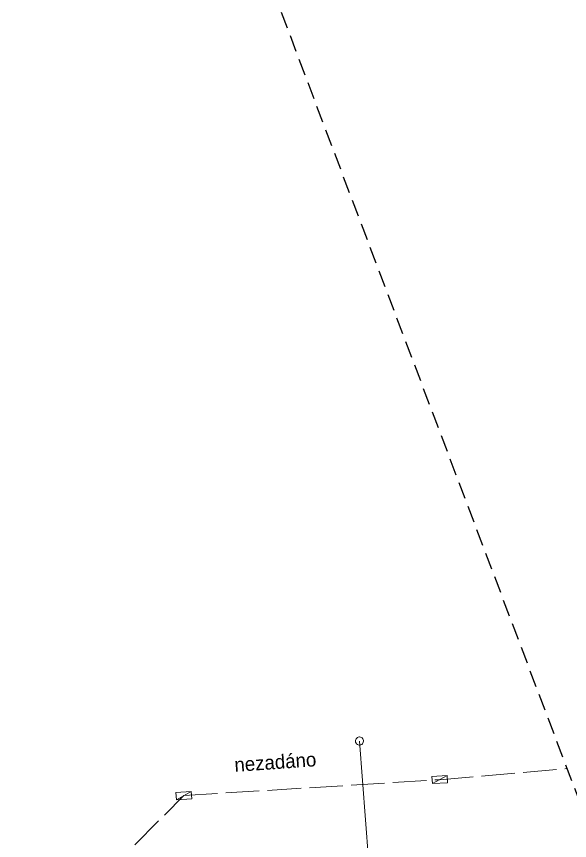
# Model space of a CAD drawing. Extents: x -732096 to -731933, y -1048703 to -1047964.
# Drawn here: x -732035.87 to -732004.18, y -1048462.87 to -1048415.69 of the extents above; entities that cross this region are included whole.
import ezdxf

# ---------------------------------------------------------------- set-up
doc = ezdxf.new("R2010")
doc.units = 0
doc.header["$LTSCALE"] = 0.32
doc.linetypes.add('LONG_DASHED', pattern=[7.5, 6, -1.5])
doc.linetypes.add('MEDIUM_DASHED', pattern=[4.5, 3, -1.5])
doc.layers.add('1', color=7, linetype='Continuous')
for name, color, linetype, lineweight in [('18', 7, 'Continuous', 13), ('20', 7, 'Continuous', 13), ('63', 7, 'MEDIUM_DASHED', 25), ('8', 7, 'Continuous', 13)]:
    doc.layers.add(name, color=color, linetype=linetype, lineweight=lineweight)

msp = doc.modelspace()

# ---------------------------------------------------------------- linework, layer by layer
at = {"layer": '18'}
for p, q in [((-732011.191, -1048459.152), (-732012.038, -1048459.617)), ((-732026.696, -1048460.54), (-732025.852, -1048460.069))]:
    msp.add_line(p, q, dxfattribs=at)
for points in [[(-732011.162, -1048459.563), (-732012.034, -1048459.617), (-732012.06, -1048459.206), (-732011.187, -1048459.152)], [(-732026.728, -1048460.129), (-732025.856, -1048460.069), (-732025.828, -1048460.48), (-732026.7, -1048460.54)]]:
    msp.add_lwpolyline(points, close=True, dxfattribs=at)
at = {"layer": '20', "linetype": 'LONG_DASHED'}
for p, q in [((-732011.62, -1048459.39), (-732004.323, -1048458.753)), ((-732011.62, -1048459.39), (-732004.323, -1048458.753)), ((-732026.27, -1048460.3), (-732011.62, -1048459.39)), ((-732026.27, -1048460.3), (-732011.62, -1048459.39)), ((-732035.87, -1048469.9), (-732026.27, -1048460.3)), ((-732035.87, -1048469.9), (-732026.27, -1048460.3))]:
    msp.add_line(p, q, dxfattribs=at)
at = {"layer": '63'}
msp.add_lwpolyline([(-731968.389, -1048129.392), (-732027.835, -1048396.578), (-731958.19, -1048580.745)], dxfattribs=at)
at = {"layer": '8'}
msp.add_line((-732015.629, -1048464.72), (-732016.204, -1048457.176), dxfattribs=at)
msp.add_lwpolyline([(-732016.232, -1048456.945), (-732016.283, -1048456.955), (-732016.332, -1048456.977), (-732016.374, -1048457.008), (-732016.407, -1048457.049), (-732016.431, -1048457.096), (-732016.443, -1048457.147), (-732016.444, -1048457.199), (-732016.433, -1048457.251), (-732016.41, -1048457.298), (-732016.377, -1048457.34), (-732016.335, -1048457.371), (-732016.288, -1048457.394), (-732016.236, -1048457.405), (-732016.184, -1048457.404), (-732016.133, -1048457.392), (-732016.087, -1048457.367), (-732016.046, -1048457.334), (-732016.014, -1048457.291), (-732015.994, -1048457.243), (-732015.984, -1048457.191), (-732015.986, -1048457.139), (-732016, -1048457.088), (-732016.026, -1048457.042), (-732016.061, -1048457.003), (-732016.103, -1048456.973), (-732016.152, -1048456.953), (-732016.204, -1048456.945)], close=True, dxfattribs=at)

# ---------------------------------------------------------------- texts
at = {"layer": '1'}
msp.add_text('nezadáno  ', height=0.8, rotation=4, dxfattribs=at).set_placement((-732023.354, -1048458.945))

doc.saveas('drawing.dxf')
